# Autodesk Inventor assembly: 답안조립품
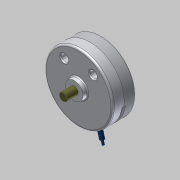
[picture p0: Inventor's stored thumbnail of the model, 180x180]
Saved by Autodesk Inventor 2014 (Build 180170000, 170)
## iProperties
Created: 2015-06
Part Number: 답안조립품
Document SubType Name: Assembly
Designer: MYHOME
Author: MYHOME
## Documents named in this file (9)
- C:\Documents and Settings\MYHOME\바탕 화면\450631V1034\답안조립품.iam
- C:\Documents and Settings\MYHOME\바탕 화면\450631V1034\본체.ipt
- C:\Documents and Settings\MYHOME\바탕 화면\450631V1034\덮개.ipt
- C:\Documents and Settings\MYHOME\바탕 화면\450631V1034\베어링62_22.ipt
- C:\Documents and Settings\MYHOME\바탕 화면\450631V1034\축.ipt
- C:\Documents and Settings\MYHOME\바탕 화면\450631V1034\멈춤링.ipt
- C:\Documents and Settings\MYHOME\바탕 화면\450631V1034\슬라이더2.ipt
- C:\Documents and Settings\MYHOME\바탕 화면\450631V1034\슬라이더.ipt
- C:\Documents and Settings\MYHOME\바탕 화면\450631V1034\평행핀.ipt
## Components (5 placed, 3 different names)
1. KS B 2023 62/22 - 22 x 50 x 14:1
2. KS B 2023 62/22 - 22 x 50 x 14:2
3. KS B 1336 22 x 1.2:1
4. KS B 1336 22 x 1.2:2
5. KS B 1320 B B 5 x  20:1
